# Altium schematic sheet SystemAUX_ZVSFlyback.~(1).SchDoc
size 431 x 279 mm; Date: Not shown in title block; ApprovedBy: Not shown in title block; CheckedBy: Not shown in title block; Author: Not shown in title block; CompanyName: Not shown in title block; Engineer: Not shown in title block; Organization: Not shown in title block; Address1: Not shown in title block; Address2: Not shown in title block; Address3: Not shown in title block; Address4: Not shown in title block; DocumentNumber: 1; Revision: Use project parameter SCH_Rev; SheetNumber: 3; SheetTotal: 3; PageSetup: Record=PageOptions¦CenterHorizontal=True¦CenterVertical=True¦PrintScale=1.00¦XCorrection=1.00¦YCorrection=1.00¦PrintKind=0¦BorderSize=5000000¦LeftOffset=0¦BottomOffset=0¦Orientation=2¦PaperLength=1000¦PaperWidth=1000¦Scale=100¦PaperSource=15¦PrintQuality=600¦MediaType=1¦DitherType=10¦PaperKind=Letter¦PrintScaleMode=1
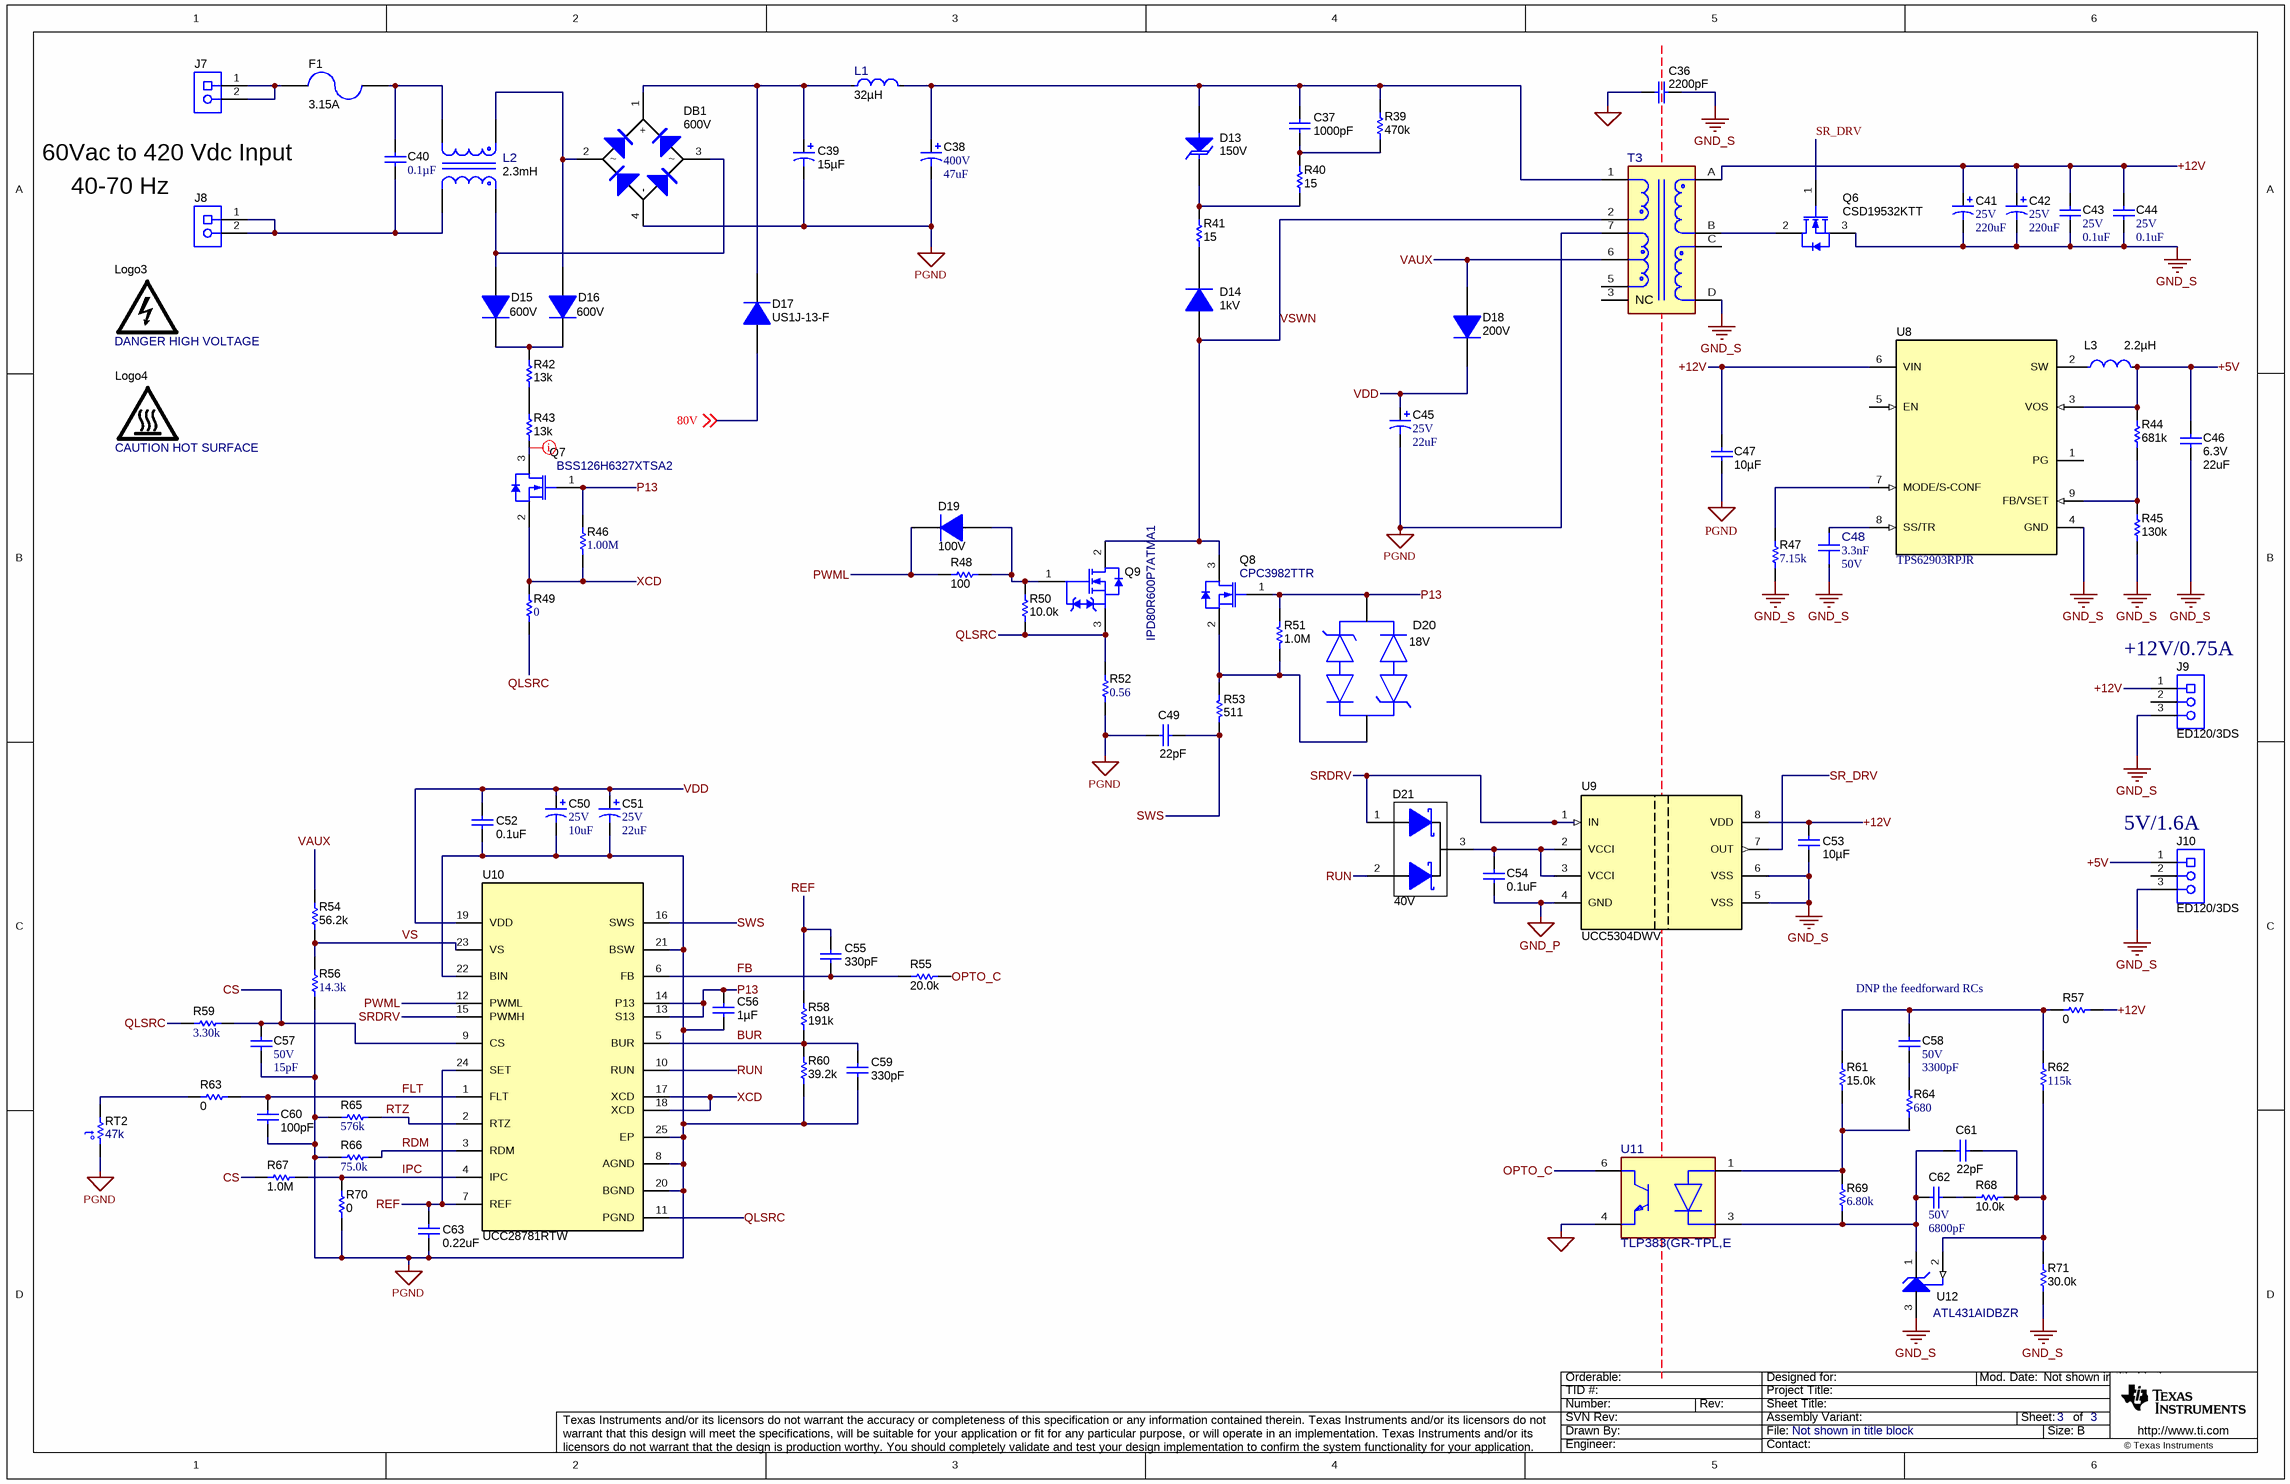
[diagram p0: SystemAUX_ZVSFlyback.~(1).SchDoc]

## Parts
C36  ValueDisplayed: 2200pF  [C900_9x13]  (hidden comment: C921U222MVVDBA7317)
C37  ValueDisplayed: 1000pF  [1206L]  (hidden comment: GRM31BR72J102KW01L)
C38  VDC_V: 400V  ValueDisplayed: 47uF  [CAPPR7.5-16x25]  (hidden comment: UCS2G470MHD)
C39  ValueDisplayed: 15µF  [UVC_1000x1600]  (hidden comment: UVC2G150MPD)
C40  ValueDisplayed: 0.1µF  [B32933_600x1500x2650]  (hidden comment: B32933A3104K000)
C41  VDC_V: 25V  ValueDisplayed: 220uF  [BT_1000x1250]  (hidden comment: UBT1E221MPD1TD)
C42  VDC_V: 25V  ValueDisplayed: 220uF  [BT_1000x1250]  (hidden comment: UBT1E221MPD1TD)
C43  VDC_V: 25V  ValueDisplayed: 0.1uF  [0603]  (hidden comment: 06033D104KAT2A)
C44  VDC_V: 25V  ValueDisplayed: 0.1uF  [0603]  (hidden comment: 06033D104KAT2A)
C45  VDC_V: 25V  ValueDisplayed: 22uF  [SM_RADIAL_D]  (hidden comment: EEE-FC1E220P)
C46  VDC_V: 6.3V  ValueDisplayed: 22uF  [0805_HV]  (hidden comment: CL21A226KQQNNNE)
C47  ValueDisplayed: 10µF  [1206_180]  (hidden comment: GCM31CR71C106KA64L)
C48  ValueDisplayed: 3.3nF  VDC_V: 50V  [FP-885012205064_0402-MFG]  (hidden comment: 885012205064)
C49  ValueDisplayed: 22pF  [0402S]  (hidden comment: GCM1555C1H220JA16D)
C50  VDC_V: 25V  ValueDisplayed: 10uF  [CAPSMT_62_D55]  (hidden comment: EMVA250ADA100MD55G)
C51  VDC_V: 25V  ValueDisplayed: 22uF  [SM_RADIAL_D]  (hidden comment: EEE-FC1E220P)
C52  ValueDisplayed: 0.1uF  [0402S]  (hidden comment: GRM155R71H104ME14D)
C53  ValueDisplayed: 10µF  [1206_180L]  (hidden comment: C1206C106J3RACAUTO)
C54  ValueDisplayed: 0.1uF  [0402S]  (hidden comment: GRM155R71H104ME14D)
C55  ValueDisplayed: 330pF  [0402S]  (hidden comment: GRM155R71H331KA01D)
C56  Cap_F: 1µF  [0603S]  (hidden comment: CGA3E1X7R1V105K080AC)
C57  VDC_V: 50V  ValueDisplayed: 15pF  [0402]  (hidden comment: CC0402JRNPO9BN150)
C58  VDC_V: 50V  ValueDisplayed: 3300pF  [0402]  (hidden comment: GRM155R71H332KA01D)
C59  ValueDisplayed: 330pF  [0402S]  (hidden comment: GRM155R71H331KA01D)
C60  ValueDisplayed: 100pF  [0402S]  (hidden comment: GRM1555C1H101JA01D)
C61  ValueDisplayed: 22pF  [0402S]  (hidden comment: GCM1555C1H220JA16D)
C62  VDC_V: 50V  ValueDisplayed: 6800pF  [0402]  (hidden comment: GRM155R71H682KA88D)
C63  ValueDisplayed: 0.22uF  [0402S]  (hidden comment: GRM155R71C224KA12D)
D13  VRWM: 150V  [SMA]  (hidden comment: SMAJ150A)
D14  Vr_V: 1kV  [SMA]  (hidden comment: MRA4007T3G)
D15  Vr_V: 600V  [TUMD2SM]  (hidden comment: RFU02VSM6STR)
D16  Vr_V: 600V  [TUMD2SM]  (hidden comment: RFU02VSM6STR)
D17  US1J-13-F  [SMA]
D18  Vr_V: 200V  [SOD-123H]  (hidden comment: CSFMT104-HF)
D19  Vr_V: 100V  [SOD-323]  (hidden comment: BAS316,115)
D20  CDSOD323-T18C  [FP-CDSOD323-T18C_SOD323-MFG]  (value not drawn)
D21  Vr_V: 40V  [SOT-323]  (hidden comment: BAS40W-05-7-F)
DB1  value 600V  [Z4-D]  (hidden comment: Z4DGP406L-HF)
F1  Irating_A: 3.15A  [FUSE_392]  (hidden comment: 39213150000)
J7  ED120/2DS  [On-Shore_ED120_2DS]  (value not drawn)
J8  ED120/2DS  [On-Shore_ED120_2DS]  (value not drawn)
J9  ED120/3DS  [On-Shore_ED120_3DS]
J10  ED120/3DS  [On-Shore_ED120_3DS]
L1  Ind_H: 32µH  [FP-7447052_PTH_D10MM0-MFG]  (hidden comment: 7447052)
L2  Ind_H: 2.3mH  [FP-RLTI-1387_PTH_CMC_0IN38_0IN60-MFG]  (hidden comment: RLTI-1387)
L3  Ind_H: 2.2µH  [FP-74438336010_SMD2-MFG]  (hidden comment: 74438336022)
Logo3  DANGER HIGH VOLTAGE  [IEC_HighVoltage_Small]  (no BOM)
Logo4  CAUTION HOT SURFACE  [IEC_HotSurface_Small]  (no BOM)
Q6  CSD19532KTT  [KTT0002A]
Q7  BSS126H6327XTSA2  [SOT-23L]
Q8  CPC3982TTR  [SOT-23L]
Q9  IPD80R600P7ATMA1  [DPAK]
R39  ValueDisplayed: 470k  [0805_HV1]  (hidden comment: CRCW0805470KJNEA)
R40  ValueDisplayed: 15  [0805_HV1]  (hidden comment: CRCW080515R0JNEA)
R41  ValueDisplayed: 15  [0805_HV1]  (hidden comment: CRCW080515R0JNEA)
R42  ValueDisplayed: 13k  [1206L]  (hidden comment: CRCW120613K0JNEA)
R43  ValueDisplayed: 13k  [1206L]  (hidden comment: CRCW120613K0JNEA)
R44  ValueDisplayed: 681k  [0402]  (hidden comment: CRCW0402681KFKED)
R45  ValueDisplayed: 130k  [0402]  (hidden comment: CRCW0402130KFKED)
R46  ValueDisplayed: 1.00M  [0603]  (hidden comment: MCT06030C1004FP500)
R47  ValueDisplayed: 7.15k  [0402]  (hidden comment: CRCW04027K15FKED)
R48  ValueDisplayed: 100  [0805_HV1]  (hidden comment: CRCW0805100RJNEA)
R49  ValueDisplayed: 0  [0603]  (hidden comment: RC0603JR-070RL)
R50  ValueDisplayed: 10.0k  [0402S]  (hidden comment: CRCW040210K0FKED)
R51  ValueDisplayed: 1.0M  [0402S]  (hidden comment: CRCW04021M00JNED)
R52  ValueDisplayed: 0.56  [1206]  (hidden comment: ERJ-8RQFR56V)
R53  ValueDisplayed: 511  [0402S]  (hidden comment: CRCW0402511RFKED)
R54  ValueDisplayed: 56.2k  [0402S]  (hidden comment: CRCW040256K2FKED)
R55  ValueDisplayed: 20.0k  [0402S]  (hidden comment: CRCW040220K0FKED)
R56  ValueDisplayed: 14.3k  [0402]  (hidden comment: CRCW040214K3FKED)
R57  ValueDisplayed: 0  [0402S]  (hidden comment: RC0402JR-070RL)
R58  ValueDisplayed: 191k  [0402S]  (hidden comment: CRCW0402191KFKED)
R59  ValueDisplayed: 3.30k  [0402]  (hidden comment: RK73H1ETTP3301F)
R60  ValueDisplayed: 39.2k  [0402S]  (hidden comment: CRCW040239K2FKED)
R61  ValueDisplayed: 15.0k  [0402S]  (hidden comment: CRCW040215K0FKED)
R62  ValueDisplayed: 115k  [0402]  (hidden comment: RC1005F1153CS)
R63  ValueDisplayed: 0  [0402S]  (hidden comment: CRCW04020000Z0EDHP)
R64  ValueDisplayed: 680  [0603]  (hidden comment: RC0603FR-07680RL)
R65  ValueDisplayed: 576k  [0402]  (hidden comment: CRCW0402576KFKED)
R66  ValueDisplayed: 75.0k  [0402]  (hidden comment: CRCW040275K0FKED)
R67  ValueDisplayed: 1.0M  [0402S]  (hidden comment: CRCW04021M00JNED)
R68  ValueDisplayed: 10.0k  [0402S]  (hidden comment: CRCW040210K0FKED)
R69  ValueDisplayed: 6.80k  [0603]  (hidden comment: RC0603FR-076K8L)
R70  ValueDisplayed: 0  [0402S]  (hidden comment: CRCW04020000Z0EDHP)
R71  ValueDisplayed: 30.0k  [0402S]  (hidden comment: CRCW040230K0FKED)
RT2  value 47k  [0603S]  (hidden comment: NCP18WB473J03RB)
T3  RLTI-1324  [FP-RLTI-1324_PTH_0IN980_0IN766-MFG]  (value not drawn)
U8  TPS62903RPJR  [RPJ0009A]
U9  UCC5304DWV  [DWV0008A]
U10  UCC28781RTW  [RTW0024B]
U11  TLP383(GR-TPL,E  [FP-TLP383(GR-TPL,E_SO6-4-MFG]
U12  ATL431AIDBZR  [DBZ0003A_L]

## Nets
GND2: C36.2 U11.4(Emitter)
GND_P: C54.2 U9.4(GND)
GND_S: C36.1 C41.2(-) C42.2(-) C43.2 C44.2 C46.2 C48.1 C53.2 J9.3 J10.3 Q6.3(S) R45.1 R47.1 R71.2 T3.D U8.4(GND) U9.5(VSS) U9.6(VSS) U12.3(ANODE)
PGND: C38.2(-) C39.2(-) C45.2(-) C47.2 C49.1 C50.2(-) C51.2(-) C52.2 C56.2 C57.2 C59.2 C60.1 C63.2 DB1.4(-) R52.1 R56.1 R60.2 R65.1 R66.1 R70.1 RT2.2 T3.7 U10.8(AGND) U10.20(BGND) U10.21(BSW) U10.22(BIN) U10.25(EP)
80V: D17.2(A) ; off-sheet 80V
+5V: C46.1 J10.1 L3.2 R44.2 U8.3(VOS)
+12V: C41.1(+) C42.1(+) C43.1 C44.1 C47.1 C53.1 J9.1 R57.1 T3.A U8.6(VIN) U9.8(VDD)
BUR: C59.1 R58.2 R60.1 U10.5(BUR)
CS: C57.1 R59.2 R67.2 U10.9(CS)
FB: C55.2 R55.1 U10.6(FB)
FLT: C60.2 R63.2 U10.1(FLT)
IPC: R67.1 R70.2 U10.4(IPC)
OPTO_C: R55.2 U11.6(Collector)
P13: C56.1 D20.2 Q7.1(G) Q8.1(G) R46.2 R51.2 U10.13(S13) U10.14(P13)
PWML: D19.1(K) R48.1 U10.12(PWML)
QLSRC: Q9.3(S) R49.1 R50.1 R52.2 R59.1 U10.11(PGND)
RDM: R66.2 U10.3(RDM)
REF: C55.1 C63.1 R58.1 U10.7(REF) U10.24(SET)
RTZ: R65.2 U10.2(RTZ)
RUN: D21.2(A) U10.10(RUN)
SR_DRV: Q6.1(G) U9.7(OUT)
SRDRV: D21.1(A) U9.1(IN) U10.15(PWMH)
SWS: C49.2 R53.1 U10.16(SWS)
VAUX: D18.2(A) R54.1 T3.6
VDD: C45.1(+) C50.1(+) C51.1(+) C52.1 D18.1(K) U10.19(VDD)
VS: R54.2 R56.2 U10.23(VS)
VSWN: D14.2(A) Q8.3(D) Q9.2(D) T3.2
XCD: Q7.2(S) R46.1 R49.2 U10.17(XCD) U10.18(XCD)
NetC37_1: C37.1 C38.1(+) D13.2(A) L1.2 R39.2 T3.1
NetC37_2: C37.2 R39.1 R40.2
NetC39_1: C39.1(+) D17.1(K) DB1.1(+) L1.1
NetC40_1: C40.1 F1.1 L2.3
NetC40_2: C40.2 J8.1 J8.2 L2.2
NetC48_2: C48.2 U8.8(SS/TR)
NetC54_1: C54.1 D21.3(K) U9.2(VCCI) U9.3(VCCI)
NetC58_1: C58.1 R57.2 R61.2 R62.2
NetC58_2: C58.2 R64.2
NetC61_1: C61.1 C62.2 R69.1 U11.3(Cathode) U12.1(CATHODE)
NetC61_2: C61.2 R62.1 R68.2 R71.1 U12.2(REF)
NetC62_1: C62.1 R68.1
NetD13_1: D13.1(K) R40.1 R41.2
NetD14_1: D14.1(K) R41.1
NetD15_1: D15.1(K) D16.1(K) R42.1
NetD15_2: D15.2(A) DB1.3 L2.1
NetD16_2: D16.2(A) DB1.2 L2.4
NetD19_2: D19.2(A) Q9.1(G) R48.2 R50.2
NetD20_1: D20.1 Q8.2(S) R51.1 R53.2
NetF1_2: F1.2 J7.1 J7.2
NetL3_1: L3.1 U8.2(SW)
NetQ6_2: Q6.2(D) T3.B
NetQ7_3: Q7.3(D) R43.2
NetR42_2: R42.2 R43.1
NetR44_1: R44.1 R45.2 U8.9(FB/VSET)
NetR47_2: R47.2 U8.7(MODE/S-CONF)
NetR61_1: R61.1 R64.1 R69.2 U11.1(Anode)
NetR63_1: R63.1 RT2.1

Not connected (* = marked no-connect by the designer): J9 2; J10 2; T3 3(NC) 5 C; U8 1(PG) 5(EN)

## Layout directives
net class HV: NetQ7_3

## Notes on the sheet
- 60Vac to 420 Vdc Input
- 40-70 Hz
- (near D20) 18V
- (near J9) +12V/0.75A
- (near J10) 5V/1.6A
- (near C58) DNP the feedforward RCs

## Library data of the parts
C36 = CMP-0078358-1: CAP, CERM, 2200 pF, X1 400 VAC/Y1 400 VAC, +/- 20%, Y5V, D9xL13mm; Manufacturer: Kemet; Cap_F: 2.2nF; SizeAreaWB_mm2: 121; VAC_X: 400V; SizeArea_mm2: 81; AEC Qualified: N; AEC Category: Q200; Value: 2200pF; TaMax_C: 125°C; SizeZ_mm: 13; TaMin_C: -40°C; SizeY_mm: 9; U/M: EA; AC_Safety: X1Y1; Cap_Case: 9x13mm
C37 = CMP-0008909-2: CAP, CERM, 1000 pF, 630 V, +/- 10%, X7R, 1206; Manufacturer: MuRata; TaMin_C: -55°C; Polarized: N; SizeAreaWB_mm2: 10.92; Value1: Unknown; U/M: EA; Value: 1000pF; TaMax_C: 125°C; SizeZ_mm: 1.35; SizeX_mm: 3.2; SizeY_mm: 1.6; Cap_Case: 1206; Value2: 630V; SizeArea_mm2: 5.12; Cap_F: 1nF; AEC Category: Q200
C38 = CMP-0010241-2: CAP, AL, 47 uF, 400 V, +/- 20%, TH; Manufacturer: Nichicon; TaMin_C: -40°C; Polarized: Y; SizeAreaWB_mm2: 324; Value1: Unknown; U/M: EA; Value: 47uF; TaMax_C: 105°C; SizeZ_mm: 25; SizeX_mm: 16; Cap_Case: Radial  16x25mm; SizeArea_mm2: 256; CompType: Capacitor; AEC Qualified: N; Cap_F: 47µF; IRMS_A: 1.18A; AEC Category: Q200
C39 = CMP-0860955-2: CAP, AL, 15 µF, 400 V, +/- 20%, AEC-Q200 Grade 2, TH; Manufacturer: Nichicon; SizeArea_mm2: 100; CompType: Capacitor; Value2: 400V; SizeZ_mm: 18; IRMS_A: 180mA; Polarized: Y; SizeX_mm: 10; Value: 15uF; TaMin_C: -40°C; AEC Grade: 2; U/M: EA; SizeAreaWB_mm2: 144; Cap_Case: 10x16; TaMax_C: 105°C; AEC Category: Q200
C40 = CMP-0077664-2: CAP, Film, 0.1 µF, X2 305 VAC, +/- 10%, AEC-Q200 Grade 2, TH; Manufacturer: TDK; TaMin_C: -40°C; Polarized: N; SizeAreaWB_mm2: 210.0; Value: 0.1uF; TaMax_C: 105°C; VAC_X: 305; SizeZ_mm: 15.0; SizeX_mm: 26.0; SizeY_mm: 5.5; SizeArea_mm2: 143.0; AEC Qualified: Y; Cap_F: 100nF; AEC Grade: 2; AEC Category: Q200
C41 C42 = CMP-0010527-1: CAP, AL, 220 uF, 25 V, +/- 20%, 0.1 ohm, TH; Manufacturer: Nichicon; TaMin_C: -40°C; ESR_ohm: 1d; Polarized: Y; SizeAreaWB_mm2: 144; Value1: 0.1 ohm; U/M: EA; Value: 220uF; TaMax_C: 125°C; SizeZ_mm: 14.5; SizeX_mm: 10; Cap_Case: 10x12.5mm; SizeArea_mm2: 100; CompType: Capacitor; Cap_F: 220µF; IRMS_A: 6.8dA; AEC Category: Q200
C43 C44 = CMP-0006758-5: CAP, CERM, 0.1 uF, 25 V, +/- 10%, X5R, 0603; Manufacturer: AVX; TaMin_C: -55°C; ESR_ohm: 0.048; Polarized: N; SizeAreaWB_mm2: 4.68; Value1: 0.048 ohm; U/M: EA; Value: 0.1uF; TaMax_C: 85°C; SizeZ_mm: 1; SizeX_mm: 1.6; SizeY_mm: 0.8; SizeArea_mm2: 1.28; Cap_F: 100nF; IRMS_A: 5.3dA; AEC Category: Q200
C45 C51 = CMP-0010654-1: CAP, AL, 22 uF, 25 V, +/- 20%, 1 ohm, SMD; Manufacturer: Panasonic; TaMin_C: -40°C; ESR_ohm: 1; Polarized: Y; SizeAreaWB_mm2: 84.28; Value1: 1 ohm; U/M: EA; Value: 22uF; TaMax_C: 105°C; SizeZ_mm: 5.4; SizeX_mm: 7.8; SizeY_mm: 6.6; Cap_Case: D; SizeArea_mm2: 51.48; CompType: Capacitor; Cap_F: 22µF; IRMS_A: 1.15dA; AEC Category: Q200
C46 = CMP-0007989-2: CAP, CERM, 22 uF, 6.3 V, +/- 10%, X5R, 0805; Manufacturer: Samsung Electro-Mechanics; TaMin_C: -55°C; Polarized: N; SizeAreaWB_mm2: 6.75; Value1: Unknown; U/M: EA; Value: 22uF; TaMax_C: 85°C; SizeZ_mm: 1.45; SizeX_mm: 2; SizeY_mm: 1.25; Cap_Case: 0805; SizeArea_mm2: 2.5; CompType: Capacitor; Cap_F: 22µF; AEC Category: Q200
C47 = GCM31CR71C106KA64L: CAP, CERM, 10 µF, 16 V,+/- 10%, X7R, AEC-Q200 Grade 1, 1206; Manufacturer: MuRata; Polarized: N; CompType: Capacitor; Value: 10uF; U/M: EA; Cap_F: 0.00001; Tolerance_%: 10; VDC_V: 16; Value2: 16V; TaMin_C: -55; TaMax_C: 125; Cap_Case: 1206; SizeArea_mm2: 5.12; SizeAreaWB_mm2: 10.92; SizeX_mm: 3.2; SizeY_mm: 1.6; SizeZ_mm: 1.8; AEC Category: Q200; AEC Qualified: Y; AEC Grade: 1; Green_Lifecycle: Active; Green_REACh: Passed
C48 = CMP-0092424-1: Cap Cer 3300pF 50V X7R 0402; Manufacturer: Wurth Electronics; TempCo: 15%; AEC Qualified: No; Value: 3.3nF; SizeZ_mm: 0.55mm; Tolerance_%: 10%
C49 C61 = CMP-0006348-2: CAP, CERM, 22 pF, 50 V, +/- 5%, C0G/NP0, AEC-Q200 Grade 1, 0402; Manufacturer: MuRata; TaMin_C: -55°C; Polarized: N; SizeAreaWB_mm2: 3; Value1: Unknown; U/M: EA; Value: 22pF; TaMax_C: 125°C; SizeZ_mm: 0.6; SizeX_mm: 1; SizeY_mm: 0.5; Cap_Case: 0402; Value2: 50V; AEC Qualified: Y; AEC Category: Q200
C50 = CMP-0010785-1: CAP, AL, 10 uF, 25 V, +/- 20%, SMD; Manufacturer: Chemi-Con; TaMin_C: -40°C; Polarized: Y; SizeAreaWB_mm2: 28.09; Value1: Unknown; U/M: EA; Value: 10uF; TaMax_C: 85°C; SizeZ_mm: 5.2; SizeX_mm: 4.3; Cap_Case: D55; SizeArea_mm2: 18.49; CompType: Capacitor; Cap_F: 10µF; IRMS_A: 24mA; AEC Category: Q200
C52 C54 = CMP-0006675-2: CAP, CERM, 0.1 uF, 50 V, +/- 20%, X7R, 0402; Manufacturer: MuRata; TaMin_C: -55°C; Polarized: N; SizeAreaWB_mm2: 3; Value1: Unknown; U/M: EA; Value: 0.1uF; TaMax_C: 125°C; SizeZ_mm: 0.6; SizeX_mm: 1; SizeY_mm: 0.5; Cap_Case: 0402; Value2: 50V; Cap_F: 100nF; AEC Category: Q200
C53 = CMP-0081062-1: CAP, CERM, 10 µF, 25 V,+/- 5%, X7R, AEC-Q200 Grade 1, 1206; Manufacturer: Kemet; TaMin_C: -55°C; Polarized: N; SizeAreaWB_mm2: 10.92; U/M: EA; Value: 10uF; TaMax_C: 125°C; SizeZ_mm: 1.8; SizeX_mm: 3.2; SizeY_mm: 1.6; Cap_Case: 1206_180; Value2: 25V; SizeArea_mm2: 5.12; AEC Qualified: Y; AEC Grade: 1; AEC Category: Q200
C55 C59 = CMP-0006687-2: CAP, CERM, 330 pF, 50 V, +/- 10%, X7R, 0402; Manufacturer: MuRata; TaMin_C: -55°C; Polarized: N; SizeAreaWB_mm2: 3; Value1: Unknown; U/M: EA; Value: 330pF; TaMax_C: 125°C; SizeZ_mm: 0.6; SizeX_mm: 1; SizeY_mm: 0.5; Cap_Case: 0402; Value2: 50V; AEC Category: Q200
C56 = CMP-0007067-4: CAP, CERM, 1 uF, 35 V, +/- 10%, X7R, AEC-Q200 Grade 1, 0603; Manufacturer: TDK; TaMin_C: -55°C; ESR_ohm: 5.522m; Polarized: N; SizeAreaWB_mm2: 4.68; Value1: 0.005522 ohm; U/M: EA; Value: 1uF; TaMax_C: 125°C; SizeZ_mm: 1; SizeX_mm: 1.6; SizeY_mm: 0.8; Cap_Case: 0603; Value2: 35V; SizeArea_mm2: 1.28; AEC Qualified: Y; IRMS_A: 2.21617A; AEC Category: Q200
C57 = CMP-0006304-2: CAP, CERM, 15 pF, 50 V, +/- 5%, C0G/NP0, 0402; Manufacturer: Yageo America; TaMin_C: -55°C; Polarized: N; SizeAreaWB_mm2: 3; Value1: Unknown; U/M: EA; Value: 15pF; TaMax_C: 125°C; SizeZ_mm: 0.6; SizeX_mm: 1; SizeY_mm: 0.5; AEC Category: Q200
C58 = CMP-0006688-2: CAP, CERM, 3300 pF, 50 V, +/- 10%, X7R, 0402; Manufacturer: MuRata; TaMin_C: -55°C; Polarized: N; SizeAreaWB_mm2: 3; Value1: Unknown; U/M: EA; Value: 3300pF; TaMax_C: 125°C; SizeZ_mm: 0.6; SizeX_mm: 1; SizeY_mm: 0.5; Cap_F: 3.3nF; AEC Category: Q200
C60 = CMP-0006410-2: CAP, CERM, 100 pF, 50 V, +/- 5%, C0G/NP0, 0402; Manufacturer: MuRata; TaMin_C: -55°C; Polarized: N; SizeAreaWB_mm2: 3; Value1: Unknown; U/M: EA; Value: 100pF; TaMax_C: 125°C; SizeZ_mm: 0.6; SizeX_mm: 1; SizeY_mm: 0.5; Cap_Case: 0402; Value2: 50V; AEC Category: Q200
C62 = CMP-0006696-2: CAP, CERM, 6800 pF, 50 V, +/- 10%, X7R, 0402; Manufacturer: MuRata; TaMin_C: -55°C; Polarized: N; SizeAreaWB_mm2: 3; Value1: Unknown; U/M: EA; Value: 6800pF; TaMax_C: 125°C; SizeZ_mm: 0.6; SizeX_mm: 1; SizeY_mm: 0.5; Cap_F: 6.8nF; AEC Category: Q200
C63 = CMP-0006648-2: CAP, CERM, 0.22 uF, 16 V, +/- 10%, X7R, 0402; Manufacturer: MuRata; TaMin_C: -55°C; Polarized: N; SizeAreaWB_mm2: 3; Value1: Unknown; U/M: EA; Value: 0.22uF; TaMax_C: 125°C; SizeZ_mm: 0.6; SizeX_mm: 1; SizeY_mm: 0.5; Cap_Case: 0402; Value2: 16V; Cap_F: 220nF; AEC Category: Q200
D13 = CMP-0084982-1: Diode, TVS, Uni, 150 V, 243 Vc, 400 W, 1.6 A, SMA; Manufacturer: Littelfuse; Vc: 243V; Ipp: 1.6A; RJA_CperW: 120; AEC Qualified: N; Value: 150V; Ppk: 400W; AEC Category: Q101; SizeArea_mm2: 16.3228; SizeAreaWB_mm2: 37.3428; SizeZ_mm: 2.87; Vbr_Max: 185V; SizeX_mm: 5.59; SizeY_mm: 2.92; Vbr_Min: 167V
D14 = CMP-0077082-2: Diode, Standard Recovery Rectifier, 1000 V, 1 A, AEC-Q101, SMA; Manufacturer: ON Semiconductor; SizeAreaWB_mm2: 37.3428; SizeArea_mm2: 16.3228; AEC Qualified: Y; TJmax_C: 175°C; AEC Category: Q101; Value: 1000V; SizeZ_mm: 2.87; Green_REACh: Passed; Io_A: 1A; Vf_V: 1.1V; SizeY_mm: 2.92; Green_Lifecycle: Active; SizeX_mm: 5.59; RJC_CperW: 16.2
D15 D16 = CMP-0080762-2: Diode, Standard Recovery Rectifier, 600 V, 0.2 A, 2x1.4mm; Manufacturer: Rohm; SizeArea_mm2: 3.5; AEC Qualified: N; SizeY_mm: 1.4; Io_A: 200mA; SizeZ_mm: 0.8; Vf_V: 2.2V; SizeAreaWB_mm2: 8.4; TJmax_C: 150°C; Value1: 0.2A; SizeX_mm: 2.5; AEC Category: Q101; Value: 600V
D17 = CMP-0077027-2: Diode, Ultrafast, 600 V, 1 A, SMA; Manufacturer: Diodes Inc.; Value: 600V; TJmax_C: 150°C; Value1: 1A; Value2: 1.7V; SizeY_mm: 2.92; Green_REACh: Passed; Green_Lifecycle: Active; SizeX_mm: 5.59; AEC Category: Q101; SizeAreaWB_mm2: 37.3428; SizeZ_mm: 2.87; SizeArea_mm2: 16.3228
D18 = CMP-0029199-2: Diode, Superfast Rectifier, 200 V, 1 A, 3.5x1.6mm; Manufacturer: Comchip Technology; Vf_V: 950mV; Value: 200V; Value1: 1A; Value2: 0.95V; TJmax_C: 150°C; SizeAreaWB_mm2: 11.7; SizeArea_mm2: 5.6; SizeX_mm: 3.5; SizeY_mm: 1.6; SizeZ_mm: 1; AEC Category: Q101; AEC Qualified: N
D19 = CMP-0029006-2: Diode, Ultrafast, 100 V, 0.25 A, SOD-323; Manufacturer: Nexperia; SizeY_mm: 1.35; Value1: 0.25A; SizeAreaWB_mm2: 8.695; SizeZ_mm: 1; Io_A: 250mA; Value2: 1.4V; SizeX_mm: 2.7; Green_REACh: Incomplete; TJmax_C: 150°C; Green_Lifecycle: Not Set; AEC Category: Q101; Value: 100V; SizeArea_mm2: 3.645
D20 = CMP-0087587-1: Diode, TVS, Bi, 18 V, SOD-323; Manufacturer: Bourns Inc.; SizeZ_mm: 1.14mm; AEC Qualified: No
D21 = CMP-0028437-2: Diode, Schottky, 40 V, 0.2 A, SOT-323; Manufacturer: Diodes Inc.; Io_A: 200mA; Green_Lifecycle: Not Set; SizeAreaWB_mm2: 10.24; Green_REACh: Incomplete; Value1: 0.2A; Value: 40V; SizeZ_mm: 1.1; SizeX_mm: 2.2; Vf_V: 800mV; Value2: 0.8V; SizeArea_mm2: 4.84; AEC Category: Q101
DB1 = Z4DGP406L-HF: Diode, P-N-Bridge, 600 V, 4 A, Z4-D; Manufacturer: Comchip Technology; U/M: EA; Vf_V: 0.95; Value1: 4A; Value2: 0.95V; Io_A: 4; Vr_V: 600; TJmax_C: 175; SizeAreaWB_mm2: 126.25; SizeArea_mm2: 85.05; SizeX_mm: 10.5; SizeY_mm: 8.1; SizeZ_mm: 1.55; AEC Category: Q101; AEC Qualified: N; Green_Lifecycle: Not Set; Green_REACh: Incomplete
F1 = CMP-0003561-2: Fuse, 3.15 A, 250VAC/VDC, TH; Manufacturer: Littelfuse; VAC_V: 250V
J7 J8 = CMP-0074910-1: Terminal Block, 5.08 mm, 2x1, Brass, TH; Manufacturer: On-Shore Technology; Pitch_mm: 5.08; Gender: Female; Shrouded: N; Row_Count: 1; Current_A: 15A; Voltage_V: 300V; Cert_CULUS: Y; CNHeader: False; CT: True; Green_Lifecycle: Not Set; Green_REACh: Incomplete
J9 J10 = CMP-0074911-1: Terminal Block, 5.08 mm, 3x1, Brass, TH; Manufacturer: On-Shore Technology; Cert_VDE: Y; CNHeader: False; Current_A: 15A; Green_Lifecycle: Not Set; Shrouded: N; Gender: Female; Green_REACh: Incomplete; Voltage_V: 300V; Row_Count: 1; Pitch_mm: 5.08; CT: True
L1 = CMP-0087546-1: WE-FI Leaded Toroidal Line Choke; Manufacturer: Wurth; SizeZ_mm: 10mm; Irms: 2.6A; DCR_ohm: 0.045; AEC Qualified: No; Symbol Name: SYM-7447052
L2 = CMP-0092946-1: Common Mode Choke, 2.3mH 35%, 0.6x0.38x0.75 IN; Manufacturer: Renco; Test Frequency: 10kHz; SizeZ_mm: 0.75inch; DCR_ohm: 0.03; AEC Qualified: No
L3 = CMP-0087867-1: 2.2µH Shielded Molded Inductor 2.4A 67mOhm Max 2-SMD; Manufacturer: Wurth Electronics; SizeZ_mm: 2mm; Material: Metal Composite; Isat: 4.3A; Symbol Name: SYM-74438336010; DCR_ohm: 0.032; AEC Grade: Grade 1; AEC Qualified: Yes
Logo3 = CMP-0074835-1: IEC 61010-1 High Voltage Warning; SymbolCreator: a0412235
Logo4 = CMP-0074837-1: IEC 61010-1 Hot Surface Warning; SymbolCreator: a0412235
Q6 = CMP-0000957-3: MOSFET, N-CH, 100 V, 136 A, KTT0002A (TO-263-2); Alternate Manufacturer: None; Manufacturer: Texas Instruments; SizeZ_mm: 4.7; ChType: N; Value2: 44 nC; VdsMax_V: 100V; SizeX_mm: 14.3; SizeAreaWB_mm2: 198.208; SizeY_mm: 10.16; Vgs_V: 20V; QgTyp_nC: 44; Value: 100V; SizeArea_mm2: 145.288; AEC Category: Q101; IdsMax_A: 136A
Q7 = CMP-0067574-2: MOSFET, N-CH, Depletion Mode, 100 V, 0.17 A, AEC-Q101, SOT-23; Manufacturer: Infineon Technologies; Alternate Manufacturer: None; ChType: N; Value: 600V; Value1: ? ohm; Value2: 1.4 nC; QgTyp_nC: 1.4; Vgs_V: 20V; IdsMax_A: 21mA; SizeAreaWB_mm2: 14.0; SizeArea_mm2: 7.5; SizeX_mm: 2.5; SizeY_mm: 3.0; SizeZ_mm: 1.1; AEC Category: Q101; AEC Qualified: Y
Q8 = CMP-0081263-2: MOSFET, N-CH, Depletion Mode, 800 V, SOT-23; Alternate Manufacturer: None; Manufacturer: IXYS; SizeAreaWB_mm2: 14; Vgs_V: 15V; Value1: ? ohm; VdsMax_V: 800V; Value: 800V; SizeZ_mm: 1.1; SizeX_mm: 2.5; SizeY_mm: 3; Value2: ? nC; SizeArea_mm2: 7.5; ChType: N; AEC Category: Q101
Q9 = CMP-0083711-2: MOSFET, N-CH, 800 V, 8 A, DPAK; Manufacturer: Infineon Technologies; Alternate Manufacturer: None; AEC Qualified: N; Vgs_V: 20V; SizeY_mm: 6.54; VdsMax_V: 800V; IdsMax_A: 8A; SizeX_mm: 9.91; Value2: 20 nC; AEC Category: Q101; ChMode: Enhancement; SizeAreaWB_mm2: 101.7114; Value1: ? ohm; SizeArea_mm2: 64.8114; Value: 800V; SizeZ_mm: 2.29; QgTyp_nC: 20
R39 = CMP-0020554-3: RES, 470 k, 5%, 0.125 W, AEC-Q200 Grade 0, 0805; Manufacturer: Vishay-Dale; Power_W: 125mW; TempCo: 200 ppm/C; Value: 470k; EIA_Code: E24; SizeX_mm: 2; SizeY_mm: 1.25; SizeZ_mm: 1.45; Value2: 0.125W; SizeArea_mm2: 2.5; AEC Qualified: Y; VDC_V: 150V; AEC Category: Q200; AEC Grade: 0
R40 R41 = CMP-0020464-3: RES, 15, 5%, 0.125 W, AEC-Q200 Grade 0, 0805; Manufacturer: Vishay-Dale; Power_W: 125mW; TempCo: 200 ppm/C; Value_Code: 15R0; Value: 15; EIA_Code: E24; SizeX_mm: 2; SizeY_mm: 1.25; SizeZ_mm: 1.45; Value2: 0.125W; SizeArea_mm2: 2.5; AEC Qualified: Y; VDC_V: 150V; AEC Category: Q200; AEC Grade: 0
R42 R43 = CMP-0018589-3: RES, 13 k, 5%, 0.25 W, AEC-Q200 Grade 0, 1206; Manufacturer: Vishay-Dale; Power_W: 250mW; TempCo: 200 ppm/C; Value_Code: 13k0; Value: 13k; EIA_Code: E24; SizeX_mm: 3.2; SizeY_mm: 1.6; SizeZ_mm: 1.35; Value2: 0.25W; SizeArea_mm2: 5.12; AEC Qualified: Y; VDC_V: 200V; AEC Category: Q200; AEC Grade: 0
R44 = CMP-0026504-2: RES, 681 k, 1%, 0.063 W, AEC-Q200 Grade 0, 0402; Manufacturer: Vishay-Dale; Power_W: 63mW; TempCo: 100 ppm/C; Value: 681k; EIA_Code: E96; SizeX_mm: 1; SizeY_mm: 0.5; SizeZ_mm: 0.6; Value2: 0.063W; CompType: Resistor; AEC Qualified: Y; VDC_V: 50V; AEC Category: Q200; AEC Grade: 0
R45 = CMP-0025997-3: RES, 130 k, 1%, 0.063 W, AEC-Q200 Grade 0, 0402; Manufacturer: Vishay-Dale; Power_W: 63mW; TempCo: 100 ppm/C; Value: 130k; EIA_Code: E96; SizeX_mm: 1; SizeY_mm: 0.5; SizeZ_mm: 0.6; Value2: 0.063W; CompType: Resistor; AEC Qualified: Y; VDC_V: 50V; AEC Category: Q200; AEC Grade: 0
R46 = CMP-0022731-2: RES, 1.00 M, 1%, 0.125 W, 0603; Manufacturer: Vishay/Beyschlag; Power_W: 125mW; TempCo: 50 ppm/C; Value_Code: 1M00; U/M: EA; Value: 1.00Meg; EIA_Code: E96; Res_ohm: 1M; SizeX_mm: 1.6; SizeY_mm: 0.8; SizeZ_mm: 1; Value2: 0.125W; SizeArea_mm2: 1.28; AEC Qualified: N; VDC_V: 75V; AEC Category: Q200
R47 = CMP-0026553-2: RES, 7.15 k, 1%, 0.063 W, AEC-Q200 Grade 0, 0402; Manufacturer: Vishay-Dale; Power_W: 63mW; TempCo: 100 ppm/C; Value_Code: 7k15; Value: 7.15k; EIA_Code: E96; SizeX_mm: 1; SizeY_mm: 0.5; SizeZ_mm: 0.6; Value2: 0.063W; AEC Qualified: Y; VDC_V: 50V; AEC Category: Q200; AEC Grade: 0
R48 = CMP-0020445-3: RES, 100, 5%, 0.125 W, AEC-Q200 Grade 0, 0805; Manufacturer: Vishay-Dale; Power_W: 125mW; TempCo: 200 ppm/C; Value_Code: 100R; Value: 100; EIA_Code: E24; SizeX_mm: 2; SizeY_mm: 1.25; SizeZ_mm: 1.45; Value2: 0.125W; SizeArea_mm2: 2.5; AEC Qualified: Y; VDC_V: 150V; AEC Category: Q200; AEC Grade: 0
R49 = CMP-0025885-5: RES, 0, 5%, 0.1 W, 0603; Manufacturer: Yageo; Power_W: 100mW; TempCo: 200 ppm/C; Value_Code: 0000; Value: 0; EIA_Code: E24; SizeX_mm: 1.6; SizeZ_mm: 1; Value2: 0.1W; SizeArea_mm2: 1.28; AEC Qualified: N; VDC_V: 75V; AEC Category: Q200; SizeY_mm: 0.8; SizeAreaWB_mm2: 4.68
R50 R68 = CMP-0025958-3: RES, 10.0 k, 1%, 0.063 W, AEC-Q200 Grade 0, 0402; Manufacturer: Vishay-Dale; Power_W: 63mW; TempCo: 100 ppm/C; Value_Code: 10k0; Value: 10.0k; EIA_Code: E96; Res_ohm: 10k; SizeX_mm: 1; SizeY_mm: 0.5; SizeZ_mm: 0.6; Value2: 0.063W; AEC Qualified: Y; VDC_V: 50V; AEC Category: Q200; AEC Grade: 0
R51 = CMP-0026859-2: RES, 1.0 M, 5%, 0.063 W, AEC-Q200 Grade 0, 0402; Manufacturer: Vishay-Dale; Value: 1.0Meg; Res_ohm: 1M; Value_Code: 1M00; Power_W: 63mW; Value2: 0.063W; VDC_V: 50V; TempCo: 200 ppm/C; SizeArea_mm2: 0.5; SizeX_mm: 1; SizeZ_mm: 0.6; EIA_Code: E24; AEC Category: Q200; AEC Qualified: Y; AEC Grade: 0
R52 = CMP-0017792-3: RES, 0.56, 1%, 0.25 W, AEC-Q200 Grade 0, 1206; Manufacturer: Panasonic; Power_W: 250mW; TempCo: 250 ppm/C; Value_Code: R560; Value: 0.56; EIA_Code: E96; SizeX_mm: 3.2; SizeY_mm: 1.6; SizeZ_mm: 1.35; Value2: 0.25W; SizeArea_mm2: 5.12; AEC Qualified: Y; AEC Category: Q200; AEC Grade: 0; SizeAreaWB_mm2: 10.92
R53 = CMP-0026436-2: RES, 511, 1%, 0.063 W, AEC-Q200 Grade 0, 0402; Manufacturer: Vishay-Dale; Power_W: 63mW; TempCo: 100 ppm/C; Value_Code: 511R; Value: 511; EIA_Code: E96; SizeX_mm: 1; SizeY_mm: 0.5; SizeZ_mm: 0.6; Value2: 0.063W; AEC Qualified: Y; VDC_V: 50V; AEC Category: Q200; AEC Grade: 0
R54 = CMP-0026453-2: RES, 56.2 k, 1%, 0.063 W, AEC-Q200 Grade 0, 0402; Manufacturer: Vishay-Dale; Power_W: 63mW; TempCo: 100 ppm/C; Value_Code: 56k2; Value: 56.2k; EIA_Code: E96; SizeX_mm: 1; SizeY_mm: 0.5; SizeZ_mm: 0.6; Value2: 0.063W; AEC Qualified: Y; VDC_V: 50V; AEC Category: Q200; AEC Grade: 0
R55 = CMP-0026162-2: RES, 20.0 k, 1%, 0.063 W, AEC-Q200 Grade 0, 0402; Manufacturer: Vishay-Dale; Power_W: 63mW; TempCo: 100 ppm/C; Value_Code: 20k0; Value: 20.0k; EIA_Code: E96; Res_ohm: 20k; SizeX_mm: 1; SizeY_mm: 0.5; SizeZ_mm: 0.6; Value2: 0.063W; AEC Qualified: Y; VDC_V: 50V; AEC Category: Q200; AEC Grade: 0
R56 = CMP-0026016-3: RES, 14.3 k, 1%, 0.063 W, AEC-Q200 Grade 0, 0402; Manufacturer: Vishay-Dale; Power_W: 63mW; TempCo: 100 ppm/C; Value_Code: 14k3; Value: 14.3k; EIA_Code: E96; SizeX_mm: 1; SizeY_mm: 0.5; SizeZ_mm: 0.6; Value2: 0.063W; AEC Qualified: Y; VDC_V: 50V; AEC Category: Q200; AEC Grade: 0
R57 = CMP-0027004-2: RES, 0, 5%, 0.063 W, 0402; Manufacturer: Yageo America; Power_W: 63mW; TempCo: 200 ppm/C; Value_Code: 0000; U/M: EA; Value: 0; EIA_Code: E24; SizeX_mm: 1; SizeY_mm: 0.5; SizeZ_mm: 0.6; Value2: 0.063W; VDC_V: 50V; AEC Category: Q200
R58 = CMP-0026063-3: RES, 191 k, 1%, 0.063 W, AEC-Q200 Grade 0, 0402; Manufacturer: Vishay-Dale; Power_W: 63mW; TempCo: 100 ppm/C; Value: 191k; EIA_Code: E96; SizeX_mm: 1; SizeY_mm: 0.5; SizeZ_mm: 0.6; Value2: 0.063W; AEC Qualified: Y; VDC_V: 50V; AEC Category: Q200; AEC Grade: 0
R59 = CMP-0026750-1: RES, 3.30 k, 1%, 0.063 W, AEC-Q200 Grade 0, 0402; Manufacturer: KOA Speer; Power_W: 63mW; TempCo: 100 ppm/C; Value_Code: 3k30; U/M: EA; Value: 3.30k; Res_ohm: 3.3k; SizeX_mm: 1; SizeY_mm: 0.5; SizeZ_mm: 0.6; Value2: 0.063W; AEC Qualified: Y; VDC_V: 50V; AEC Grade: 0; AEC Category: Q200
R60 = CMP-0026327-2: RES, 39.2 k, 1%, 0.063 W, AEC-Q200 Grade 0, 0402; Manufacturer: Vishay-Dale; Power_W: 63mW; TempCo: 100 ppm/C; Value_Code: 39k2; Value: 39.2k; EIA_Code: E96; SizeX_mm: 1; SizeY_mm: 0.5; SizeZ_mm: 0.6; Value2: 0.063W; AEC Qualified: Y; VDC_V: 50V; AEC Category: Q200; AEC Grade: 0
R61 = CMP-0026027-3: RES, 15.0 k, 1%, 0.063 W, AEC-Q200 Grade 0, 0402; Manufacturer: Vishay-Dale; Power_W: 63mW; TempCo: 100 ppm/C; Value_Code: 15k0; Value: 15.0k; EIA_Code: E96; Res_ohm: 15k; SizeX_mm: 1; SizeY_mm: 0.5; SizeZ_mm: 0.6; Value2: 0.063W; AEC Qualified: Y; VDC_V: 50V; AEC Category: Q200; AEC Grade: 0
R62 = CMP-0077547-1: RES, 115 k, 1%, 0.0625 W, 0402; Manufacturer: Samsung Electro-Mechanics; Power_W: 62.5mW; TempCo: 300 ppm/C; U/M: EA; Value: 115k; EIA_Code: E96; SizeX_mm: 1.0; SizeY_mm: 0.5; SizeZ_mm: 0.6; AEC Qualified: N; VDC_V: 50V; AEC Category: Q200
R63 R70 = CMP-0081856-1: RES, 0, 0%, 0.2 W, AEC-Q200 Grade 0, 0402; Manufacturer: Vishay-Dale; SizeAreaWB_mm2: 3; SizeArea_mm2: 0.5; AEC Qualified: Y; AEC Category: Q200; Value: 0; SizeZ_mm: 0.6; Power_W: 200mW; VDC_V: 50V; Value2: 0.2W; SizeX_mm: 1
R64 = CMP-0023235-5: RES, 680, 1%, 0.1 W, 0603; Manufacturer: Yageo; Power_W: 100mW; TempCo: 100 ppm/C; Value_Code: 680R; Value: 680; SizeX_mm: 1.6; SizeY_mm: 0.8; SizeZ_mm: 1; Value2: 0.1W; SizeArea_mm2: 1.28; AEC Qualified: N; VDC_V: 75V; AEC Category: Q200; SizeAreaWB_mm2: 4.68
R65 = CMP-0026455-2: RES, 576 k, 1%, 0.063 W, AEC-Q200 Grade 0, 0402; Manufacturer: Vishay-Dale; Power_W: 63mW; TempCo: 100 ppm/C; Value: 576k; EIA_Code: E96; SizeX_mm: 1; SizeY_mm: 0.5; SizeZ_mm: 0.6; Value2: 0.063W; AEC Qualified: Y; VDC_V: 50V; AEC Category: Q200; AEC Grade: 0
R66 = CMP-0026543-2: RES, 75.0 k, 1%, 0.063 W, AEC-Q200 Grade 0, 0402; Manufacturer: Vishay-Dale; Power_W: 63mW; TempCo: 100 ppm/C; Value_Code: 75k0; Value: 75.0k; EIA_Code: E96; Res_ohm: 75k; SizeX_mm: 1; SizeY_mm: 0.5; SizeZ_mm: 0.6; Value2: 0.063W; AEC Qualified: Y; VDC_V: 50V; AEC Category: Q200; AEC Grade: 0
R67 = CMP-0026859-2: RES, 1.0 M, 5%, 0.063 W, AEC-Q200 Grade 0, 0402; Manufacturer: Vishay-Dale; Power_W: 63mW; TempCo: 200 ppm/C; Value_Code: 1M00; Value: 1.0Meg; EIA_Code: E24; Res_ohm: 1M; SizeX_mm: 1; SizeY_mm: 0.5; SizeZ_mm: 0.6; Value2: 0.063W; AEC Qualified: Y; VDC_V: 50V; AEC Category: Q200; AEC Grade: 0
R69 = CMP-0023253-5: RES, 6.80 k, 1%, 0.1 W, 0603; Manufacturer: Yageo; Power_W: 100mW; TempCo: 100 ppm/C; Value_Code: 6k80; Value: 6.80k; Res_ohm: 6.8k; SizeX_mm: 1.6; SizeY_mm: 0.8; SizeZ_mm: 1; Value2: 0.1W; SizeArea_mm2: 1.28; AEC Qualified: N; VDC_V: 75V; AEC Category: Q200; SizeAreaWB_mm2: 4.68
R71 = CMP-0078244-2: RES, 30.0 k, 1%, 0.063 W, AEC-Q200 Grade 0, 0402; Manufacturer: Vishay-Dale; Power_W: 63mW; Green_Lifecycle: Active; TempCo: 100 ppm/C; Value_Code: 30k0; Green_REACh: Passed; Value: 30.0k; Res_ohm: 30k; SizeX_mm: 1; SizeY_mm: 0.5; SizeZ_mm: 0.6; Value2: 0.063W; AEC Qualified: Y; VDC_V: 50V; AEC Grade: 0; AEC Category: Q200
RT2 = CMP-0002523-3: Thermistor NTC, 47k ohm, 5%, 0603; Manufacturer: MuRata; TaMax_C: 125°C; SizeX_mm: 1.6; SizeY_mm: 0.8; TaMin_C: -40°C; Power_W: 100mW; SizeZ_mm: 1; SizeArea_mm2: 1.28; SizeAreaWB_mm2: 4.68; U/M: EA
T3 = CMP-0087465-1: Lm=200uH, Llk=5uH / P:S1:S2:A = 40:10:10:15; Manufacturer: Renco Electronics; AEC Qualified: No; SizeZ_mm: 0.66inch; DCR_ohm: 0.1; Ind_H: 110µH; Ns1toNp: 2.5:0.5:1:0.5:1
U8 = CMP-0084866-4: 2.9-V to 18-V, 3-A Synchronous Buck Converters, RPJ0009A (VQFN-HR-9); Alternate PartNumber: TPS62903RPJT; Alternate Manufacturer: Texas Instruments; SizeArea_mm2: 3; AEC Category: Q200; SizeX_mm: 1.5; SizeY_mm: 2; SizeAreaWB_mm2: 7.5; SizeZ_mm: 1; CompType: IC; AEC Qualified: N
U9 = CMP-0860377-2: 4-A/6-A, Single-Channel Reinforced Isolation Gate Driver with High Noise Immunity, DWV0008A (SOIC-8); Manufacturer: Texas Instruments; SizeX_mm: 11.5; SizeArea_mm2: 67.275; SizeAreaWB_mm2: 105.975; CompType: IC; SizeZ_mm: 2.8; SizeY_mm: 5.85; AEC Category: Q200; AEC Qualified: N
U10 = CMP-0086087-1: UCC28781RTW, RTW0024B (WQFN-24); Manufacturer: Texas Instruments; SizeY_mm: 4; SizeZ_mm: 0.8; AEC Category: Q200; SizeArea_mm2: 16; CompType: IC; AEC Qualified: N; SizeAreaWB_mm2: 25
U11 = CMP-0087394-2: Optoisolator Transistor Output 5000Vrms 1 Channel 6-SO; Manufacturer: Toshiba; CTR (Max): 300%; CTR (Min): 100%; SizeZ_mm: 2.3mm
U12 = CMP-0066199-1: 2.5V Low Iq Adjustable Precision Shunt Regulator, DBZ0003A (SOT-23-3); Manufacturer: Texas Instruments; SizeArea_mm2: 7.5; SizeAreaWB_mm2: 14.0; SizeX_mm: 2.5; SizeY_mm: 3.0; SizeZ_mm: 1.12; CompType: IC; U/M: EA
